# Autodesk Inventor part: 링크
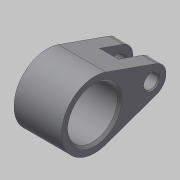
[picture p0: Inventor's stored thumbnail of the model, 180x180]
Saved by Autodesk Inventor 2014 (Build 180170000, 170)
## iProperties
Created: 2016-08
Part Number: 링크
Material: 강철, 탄소
Document SubType Name: Modeling
Designer: mduedu
Density: 7.87 g/cm^3
Appearance: 기본값
Author: mduedu
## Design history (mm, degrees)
sketch "스케치1"
  geometry: L1 (26, 5.657)-(4.667, 13.199); L2 (26, -5.657)-(4.667, -13.199); C1 r 10.5 at (0, 0); C2 r 3 at (24, 0); A1 r 14 centre (0, 0) between (4.667, 13.199) and (4.667, -13.199); A2 r 6 centre (24, 0) between (26, 5.657) and (26, -5.657); 1 further point
  constraints: 4 centre point, 4 end point, 4 point on circle, 4 tangent, 3 coincident, 1 horizontal alignment
  dimensions: "d0" = 28 diameter of A1; "d2" = 12 diameter of A2; "d3" = 24 distance of A2.centre point (0, 0); "d4" = 21 diameter of C1; "d5" = 6 diameter of C2
extrude "돌출1" new body sketch "스케치1" stored distance "d6" = 20; taper "d7" = 0 deg
sketch "스케치2"
  geometry: L1 (-10, 30)-(10, 30) reference; L2 (0, 0)-(0, 30); L3 (-4, 30)-(4, 30); L4 (4, 30)-(4, 16); L5 (4, 16)-(-4, 16); L6 (-4, 16)-(-4, 30)
  constraints: 10 end point, 2 midpoint, 2 parallel, 1 horizontal, 1 perpendicular, 1 point on line
  dimensions: "d8" = 8 distance between parallel lines of L4 L6; "d10" = 14 distance of L3.end L4.end
extrude "돌출2" cut sketch "스케치2" stored distance "d11" = 20; taper "d12" = 0 deg
chamfer "모따기1" distance "d13" = 1; stored, may be unused: second distance "d14" = 2, angle "d15" = 45 deg
chamfer "모따기2" distance "d16" = 0.5; stored, may be unused: second distance "d17" = 2, angle "d18" = 45 deg
node "솔리드1"
